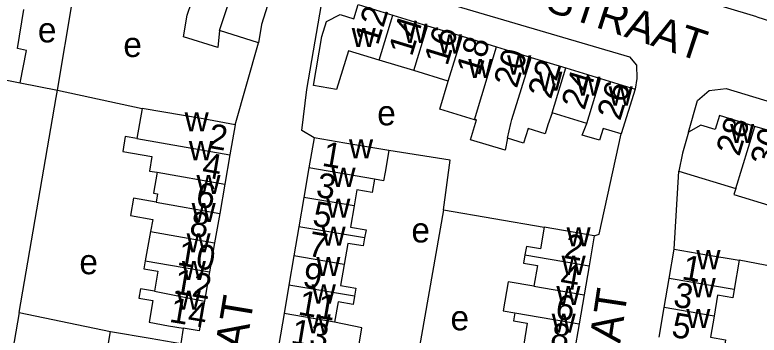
# Model space of a CAD drawing. Extents: x 159045 to 160918, y 380454 to 382516.
# Drawn here: x 160036.8 to 160156.1, y 381018.7 to 381070.1 of the extents above; entities that cross this region are included whole.
import ezdxf

# ---------------------------------------------------------------- set-up
doc = ezdxf.new("R2010")
doc.units = 0
for name, color, linetype in [('BLT_Basislijn', 7, 'Continuous'), ('BLT_Bebouwing', 7, 'Continuous'), ('BLT_Centroide', 7, 'Continuous'), ('BLT_Huisnummer', 7, 'Continuous'), ('BLT_Huisnummer_ tussenligend', 7, 'Continuous'), ('BLT_Onderverdeling_panden', 7, 'Continuous'), ('BLT_Straatnaam', 7, 'Continuous')]:
    doc.layers.add(name, color=color, linetype=linetype)

msp = doc.modelspace()

# ---------------------------------------------------------------- linework, layer by layer
at = {"layer": 'BLT_Basislijn'}
for p, q in [((160155.74, 381069.81), (160137.3, 381075.42)), ((160043.59, 381058.05), (160046.02, 381072.41)), ((160155.74, 381069.81), (160189.49, 381059.35)), ((160037.63, 381059.25), (160043.59, 381058.05)), ((160043.59, 381058.05), (160057.16, 381055.13)), ((160142.49, 381032.54), (160143.23, 381045.03)), ((160105.52, 381038.85), (160121.63, 381036.06)), ((160037.42, 381022.36), (160052.07, 381019.3)), ((160063.77, 381019.85), (160063.36, 381017.41))]:
    msp.add_line(p, q, dxfattribs=at)
for points in [[(160084.74, 381050.4), (160082.76, 381051.58), (160083.57, 381058.18), (160086.47, 381074.98), (160088.15, 381076.51), (160091.81, 381076.24), (160135.31, 381063.4), (160136.45, 381062.09), (160136.48, 381059.92), (160136.21, 381058.23)], [(160072.09, 381052.51), (160075.83, 381065.67)], [(160037.42, 381022.36), (160043.39, 381056.9), (160043.59, 381058.05)], [(160144.79, 381051.32), (160146.23, 381056.39), (160148.09, 381058.01), (160150.82, 381058.34), (160192.75, 381045.59), (160194.59, 381043.41), (160194.08, 381040.48)], [(160129.65, 381034.69), (160130.46, 381034.96), (160134.01, 381051.03)], [(160105.52, 381038.85), (160106.55, 381046.81), (160096.72, 381048.36)], [(160105.52, 381038.85), (160100.74, 381011.71), (160100.66, 381011.22)], [(160163.53, 381023.19), (160164.31, 381028.56), (160152.91, 381030.75)], [(160037.42, 381022.36), (160033.1, 380997.56), (160033.06, 380997.32)]]:
    msp.add_lwpolyline(points, dxfattribs=at)
at = {"layer": 'BLT_Bebouwing'}
for p, q in [((160097.38, 381070.09), (160102.93, 381068.4)), ((160102.93, 381068.4), (160108.48, 381066.7)), ((160108.48, 381066.7), (160114.02, 381065.01)), ((160114.02, 381065.01), (160119.57, 381063.32)), ((160100.73, 381061.19), (160095.18, 381062.88)), ((160119.57, 381063.32), (160125.12, 381061.62)), ((160125.12, 381061.62), (160130.67, 381059.93)), ((160106.27, 381059.49), (160100.73, 381061.19)), ((160130.67, 381059.93), (160136.21, 381058.23)), ((160136.21, 381058.23), (160134.01, 381051.03)), ((160128.47, 381052.72), (160122.92, 381054.41)), ((160072.09, 381052.51), (160071.24, 381047.66)), ((160160.92, 381050.58), (160155.42, 381052.25)), ((160084.74, 381050.4), (160083.92, 381045.58)), ((160071.24, 381047.66), (160070.43, 381042.97)), ((160083.92, 381045.58), (160083.11, 381040.84)), ((160143.23, 381045.03), (160152.37, 381042.25)), ((160070.43, 381042.97), (160069.61, 381038.28)), ((160083.11, 381040.84), (160082.31, 381036.14)), ((160069.61, 381038.28), (160068.79, 381033.57)), ((160082.31, 381036.14), (160081.51, 381031.46)), ((160129.65, 381034.69), (160128.83, 381029.88)), ((160068.79, 381033.57), (160067.97, 381028.88)), ((160141.69, 381027.85), (160142.49, 381032.54)), ((160081.51, 381031.46), (160080.71, 381026.77)), ((160152.91, 381030.75), (160152.1, 381026.05)), ((160128.83, 381029.88), (160128.04, 381025.21)), ((160067.97, 381028.88), (160067.15, 381024.19)), ((160140.88, 381023.15), (160141.69, 381027.85)), ((160080.71, 381026.77), (160079.94, 381022.21)), ((160128.04, 381025.21), (160127.24, 381020.56)), ((160140.06, 381018.41), (160140.88, 381023.15)), ((160127.24, 381020.56), (160126.45, 381015.93))]:
    msp.add_line(p, q, dxfattribs=at)
for points in [[(160078.53, 381075.78), (160076.33, 381068.6), (160075.83, 381065.67)], [(160037.63, 381059.25), (160038.64, 381064.45), (160037.16, 381064.74), (160038.18, 381070.98)], [(160069.59, 381067.62), (160069.33, 381064.92), (160063.81, 381066.64), (160064.39, 381070.11), (160065.06, 381072.15)], [(160095.18, 381062.88), (160090.24, 381064.39), (160088.33, 381058.15), (160084.65, 381058.78), (160086, 381066.66), (160086.74, 381069.08), (160088.94, 381070.19), (160091.14, 381069.52), (160091.83, 381071.79), (160097.38, 381070.09)], [(160075.83, 381065.67), (160069.59, 381067.62)], [(160020.45, 381062.57), (160025.36, 381061.62), (160037.63, 381059.25)], [(160110.45, 381053.31), (160104.9, 381055), (160106.27, 381059.49)], [(160057.16, 381055.13), (160056.31, 381050.28)], [(160072.09, 381052.51), (160066.93, 381053.44), (160057.16, 381055.13)], [(160122.92, 381054.41), (160122.25, 381052.51), (160121.8, 381051.04), (160119.06, 381051.88), (160118.35, 381049.56), (160115.78, 381050.35)], [(160115.78, 381050.35), (160115.36, 381048.4), (160109.82, 381050.09), (160110.79, 381053.27), (160110.45, 381053.31)], [(160155.42, 381052.25), (160149.77, 381053.98), (160149.09, 381051.74), (160146.78, 381052.43), (160144.79, 381051.32)], [(160134.01, 381051.03), (160131.09, 381051.92), (160130.51, 381050.01), (160127.76, 381050.85), (160128.47, 381052.72)], [(160144.79, 381051.32), (160143.8, 381047.92), (160143.23, 381045.03)], [(160056.31, 381050.28), (160054.45, 381050.6), (160054.05, 381048.2), (160058.74, 381047.42), (160058.35, 381045.05), (160059.59, 381044.87)], [(160096.72, 381048.36), (160089.67, 381049.56), (160084.74, 381050.4)], [(160096.72, 381048.36), (160096.12, 381044.87), (160095.9, 381043.53), (160094.42, 381043.79)], [(160059.59, 381044.87), (160059, 381041.51), (160059.64, 381041.4), (160059.41, 381040.07)], [(160094.42, 381043.79), (160094.06, 381041.64), (160091.59, 381042.06), (160091.15, 381039.47)], [(160152.37, 381042.25), (160152.08, 381041.29), (160157.68, 381039.59), (160158.85, 381043.43)], [(160059.41, 381040.07), (160055.77, 381040.71), (160055.28, 381037.93), (160058.89, 381037.3), (160058.53, 381035.37)], [(160091.15, 381039.47), (160090.57, 381036.06), (160093.07, 381035.63), (160092.85, 381034.34)], [(160058.53, 381035.37), (160057.66, 381030.69)], [(160121.63, 381036.06), (160121.03, 381032.57), (160118.79, 381032.96), (160118.56, 381031.63)], [(160129.65, 381034.69), (160124.73, 381035.53), (160121.63, 381036.06)], [(160092.85, 381034.34), (160092.62, 381033.05), (160090.15, 381033.47), (160089.57, 381030.08)], [(160118.56, 381031.63), (160118.34, 381030.31), (160120.55, 381029.93), (160119.98, 381026.59)], [(160142.49, 381032.54), (160147.42, 381031.69), (160152.91, 381030.75)], [(160057.66, 381030.69), (160057.43, 381029.36), (160059.69, 381028.98), (160059.16, 381025.78)], [(160089.57, 381030.08), (160088.99, 381026.7), (160091.46, 381026.27), (160091.24, 381024.98)], [(160119.98, 381026.59), (160115.84, 381027.28), (160115.05, 381022.64), (160116.96, 381022.32)], [(160059.16, 381025.78), (160056.88, 381026.18), (160056.63, 381024.69), (160058.87, 381024.31), (160058.28, 381020.8), (160061.38, 381020.25), (160063.77, 381019.85)], [(160152.1, 381026.05), (160151.87, 381024.73), (160149.46, 381025.15), (160148.88, 381021.77)], [(160091.24, 381024.98), (160091.02, 381023.68), (160088.58, 381024.1), (160088.02, 381020.83)], [(160067.15, 381024.19), (160066.32, 381019.42), (160063.77, 381019.85)], [(160079.94, 381022.21), (160079.09, 381017.26), (160081.65, 381016.82)], [(160116.96, 381022.32), (160116.73, 381021.01), (160118.94, 381020.64), (160118.38, 381017.31)], [(160081.65, 381016.82), (160084.02, 381016.42), (160091.58, 381015.03), (160092.42, 381019.92), (160088.02, 381020.83)], [(160148.88, 381021.77), (160148.3, 381018.39), (160150.73, 381017.97), (160150.49, 381016.62)], [(160051.3, 381013.55), (160051.12, 381013.58), (160052.07, 381019.3)], [(160052.07, 381019.3), (160058.43, 381018.24), (160063.36, 381017.41)]]:
    msp.add_lwpolyline(points, dxfattribs=at)
at = {"layer": 'BLT_Onderverdeling_panden'}
for p, q in [((160069.59, 381067.62), (160072.82, 381077.55)), ((160095.18, 381062.88), (160097.38, 381070.09)), ((160100.73, 381061.19), (160102.93, 381068.4)), ((160106.27, 381059.49), (160108.48, 381066.7)), ((160110.45, 381053.31), (160114.02, 381065.01)), ((160122.92, 381054.41), (160125.12, 381061.62)), ((160128.47, 381052.72), (160130.67, 381059.93)), ((160152.37, 381042.25), (160155.42, 381052.25)), ((160056.31, 381050.28), (160071.24, 381047.66)), ((160059.59, 381044.87), (160070.43, 381042.97)), ((160094.42, 381043.79), (160083.92, 381045.58)), ((160059.41, 381040.07), (160069.61, 381038.28)), ((160091.15, 381039.47), (160083.11, 381040.84)), ((160058.53, 381035.37), (160068.79, 381033.57)), ((160092.85, 381034.34), (160082.31, 381036.14)), ((160118.56, 381031.63), (160128.83, 381029.88)), ((160057.66, 381030.69), (160067.97, 381028.88)), ((160089.57, 381030.08), (160081.51, 381031.46)), ((160152.1, 381026.05), (160141.69, 381027.85)), ((160059.16, 381025.78), (160067.15, 381024.19)), ((160091.24, 381024.98), (160080.71, 381026.77)), ((160119.98, 381026.59), (160128.04, 381025.21)), ((160088.02, 381020.83), (160079.94, 381022.21)), ((160116.96, 381022.32), (160127.24, 381020.56)), ((160148.88, 381021.77), (160140.88, 381023.15))]:
    msp.add_line(p, q, dxfattribs=at)
msp.add_lwpolyline([(160115.78, 381050.35), (160116.29, 381052.73), (160116.48, 381053.34), (160119.57, 381063.32)], dxfattribs=at)

# ---------------------------------------------------------------- texts
at = {"layer": 'BLT_Centroide'}
for s, p in [('e', (160040.45, 381065.73)), ('w', (160099.05, 381065.64)), ('w', (160090.77, 381064.97)), ('e', (160054.15, 381063.38)), ('w', (160104.59, 381063.94)), ('w', (160109.47, 381060)), ('w', (160115.7, 381060.56)), ('w', (160120.7, 381057.97)), ('w', (160126.8, 381057.16)), ('w', (160131.98, 381055.59)), ('e', (160094.87, 381052.41)), ('w', (160063.98, 381051.44)), ('w', (160151.45, 381049.58)), ('w', (160064.66, 381046.81)), ('w', (160090.34, 381047.09)), ('w', (160087.53, 381042.53)), ('w', (160065.88, 381041.38)), ('w', (160065.1, 381036.88)), ('w', (160086.7, 381037.59)), ('e', (160100.35, 381033.61)), ('w', (160085.94, 381033.09)), ('w', (160125.23, 381032.97)), ('w', (160064.29, 381032.03)), ('e', (160047.1, 381028.51)), ('w', (160146.05, 381029.31)), ('w', (160063.53, 381027.59)), ('w', (160085.1, 381028.22)), ('w', (160124.43, 381028.41)), ('w', (160084.37, 381023.81)), ('w', (160145.28, 381024.81)), ('w', (160062.71, 381022.81)), ('w', (160123.6, 381023.56)), ('w', (160083.55, 381019.03)), ('e', (160106.62, 381019.51)), ('w', (160122.84, 381019.12)), ('w', (160144.43, 381019.88))]:
    msp.add_text(s, height=4, dxfattribs=at).set_placement(p)
at = {"layer": 'BLT_Huisnummer'}
for s, rotation, p in [('12', 73.0225, (160094.97, 381065.12)), ('16', 73.0152, (160106.11, 381061.83)), ('20', 73.0197, (160117.25, 381058.23)), ('26', 73.0197, (160133.82, 381053.02)), ('28', 73.0699, (160152.92, 381047.3)), ('2', 350.5016, (160067.56, 381048.82)), ('1', 350.3272, (160085.87, 381045.94)), ('6', 350.5065, (160065.62, 381039.43)), ('5', 350.3315, (160084.33, 381036.35)), ('2', 350.2993, (160124.68, 381031.14)), ('10', 350.4961, (160062.66, 381030.02)), ('9', 350.332, (160082.74, 381026.55)), ('1', 350.2245, (160143.57, 381027.73)), ('14', 350.3735, (160061.38, 381020.89)), ('6', 350.3089, (160123.27, 381021.44)), ('5', 350.2228, (160141.91, 381018.49)), ('13', 350.3873, (160080.86, 381017.44))]:
    msp.add_text(s, height=4, rotation=rotation, dxfattribs=at).set_placement(p)
at = {"layer": 'BLT_Huisnummer_ tussenligend'}
for s, rotation, p in [('14', 73.0225, (160100.43, 381063.35)), ('18', 73.0152, (160111.27, 381060.18)), ('22', 73.0197, (160122.73, 381056.49)), ('24', 73.0197, (160128.1, 381054.72)), ('30', 73.0699, (160158.39, 381045.54)), ('4', 350.5016, (160066.62, 381044.17)), ('3', 350.3272, (160084.91, 381040.96)), ('8', 350.5065, (160064.6, 381034.78)), ('7', 350.3315, (160083.59, 381031.5)), ('4', 350.2993, (160124.05, 381026.39)), ('12', 350.4961, (160062.06, 381025.47)), ('3', 350.2245, (160142.2, 381023.36)), ('11', 350.332, (160082.03, 381022.05)), ('8', 350.3089, (160122.45, 381016.89))]:
    msp.add_text(s, height=4, rotation=rotation, dxfattribs=at).set_placement(p)
at = {"layer": 'BLT_Straatnaam'}
for s, height, rotation, p in [('VERHULSTSTRAAT', 5, 341.7344, (160087.74, 381082.07)), ('SAMUEL DE LANGESTRAAT', 4.9999, 81.4087, (160121.73, 380937.22)), ('DIEPENBROCKSTRAAT', 5, 80.5206, (160062.81, 380950.53))]:
    msp.add_text(s, height=height, rotation=rotation, dxfattribs=at).set_placement(p)

doc.saveas('drawing.dxf')
